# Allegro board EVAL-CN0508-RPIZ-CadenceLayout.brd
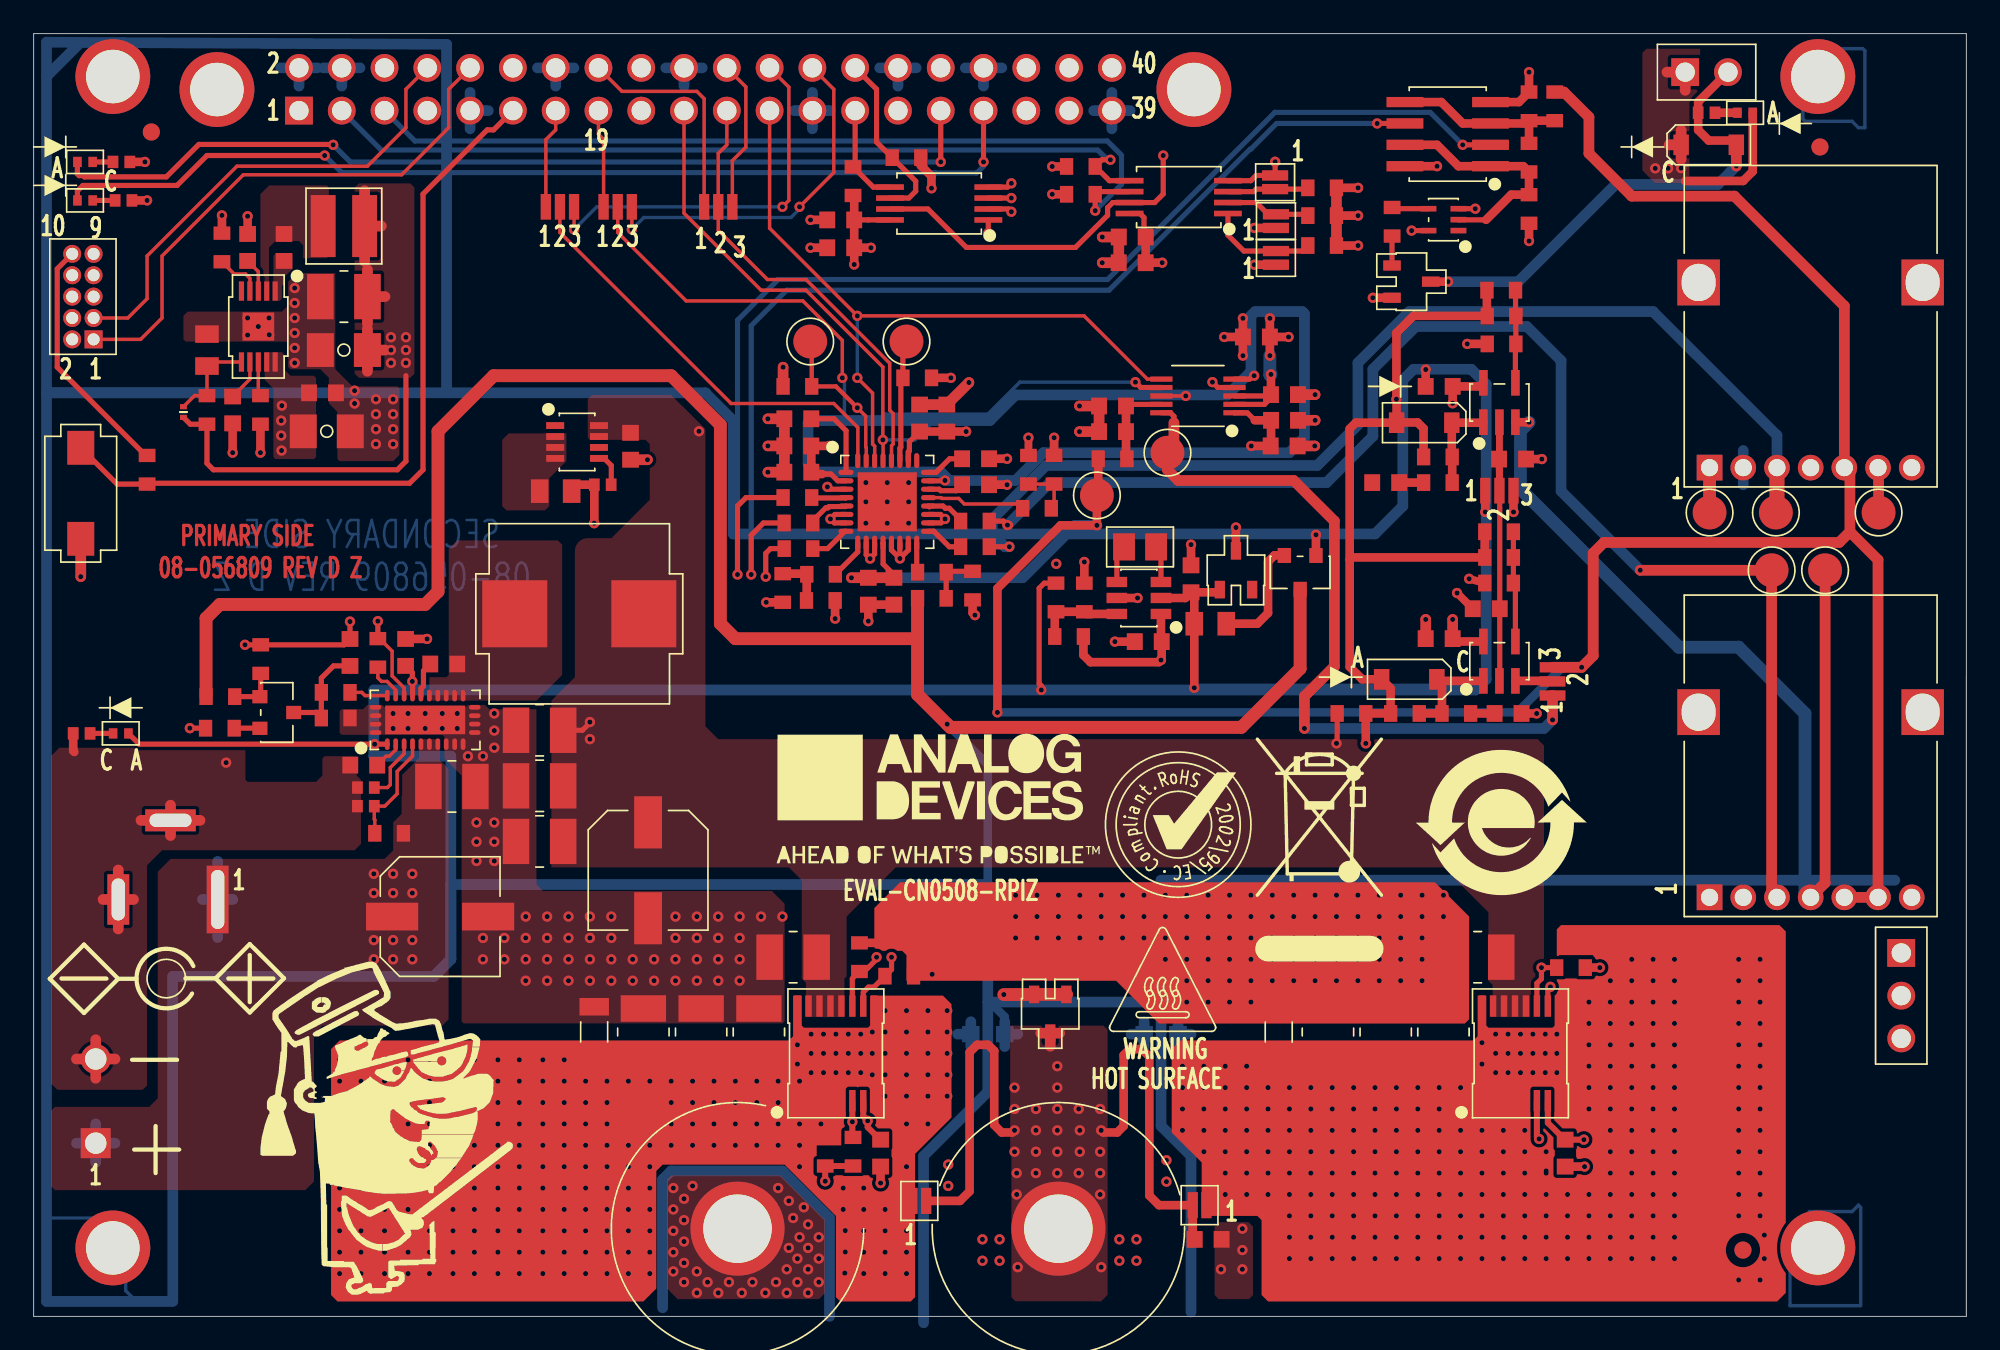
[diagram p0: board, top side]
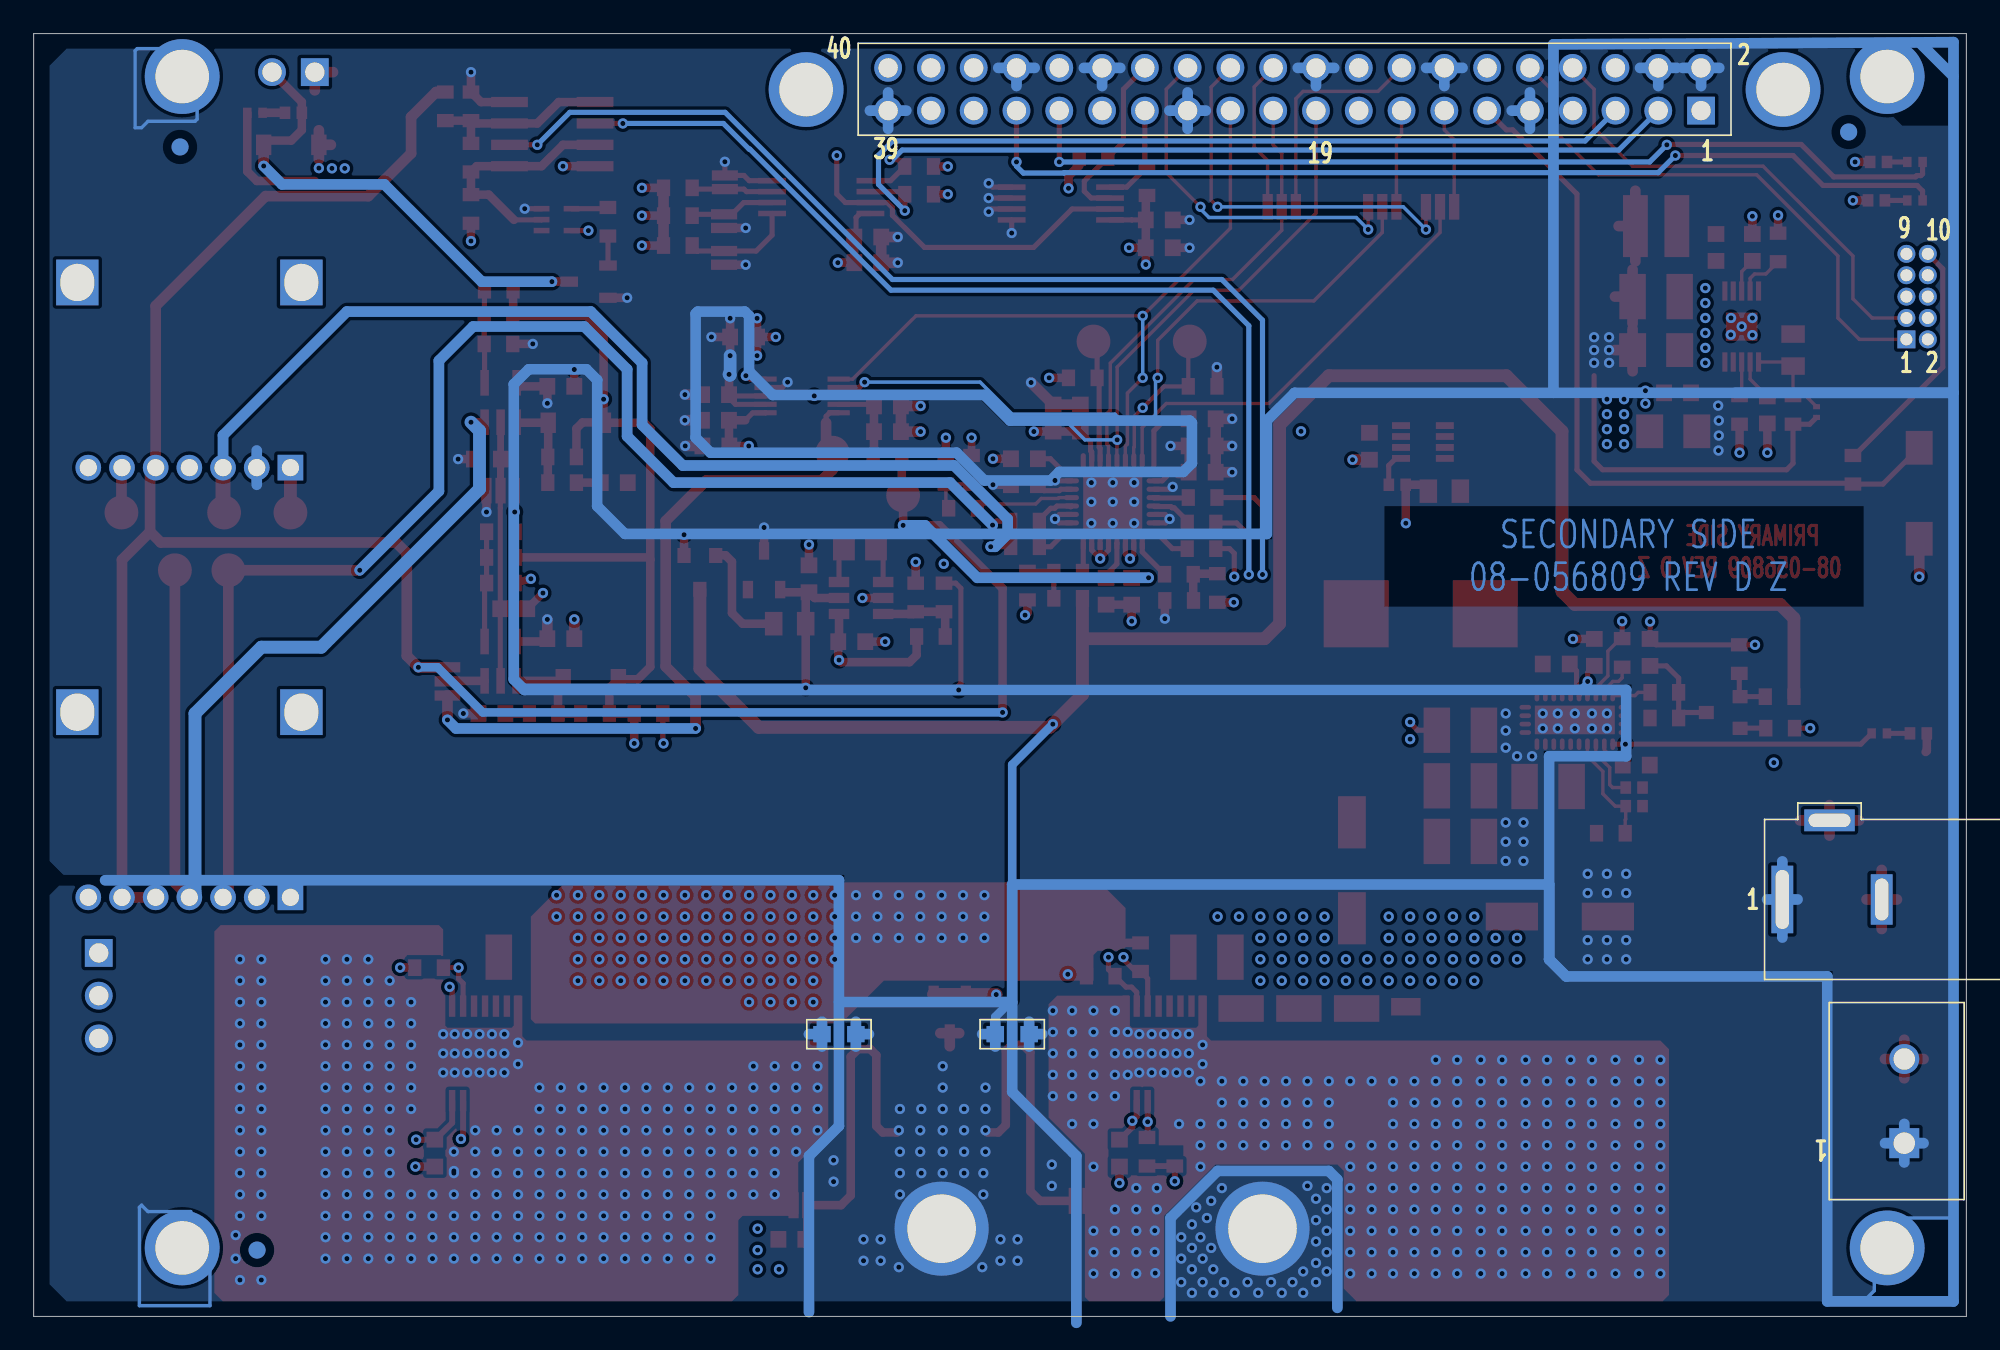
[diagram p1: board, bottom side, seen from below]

Outline 114.73 x 76.2 mm; copper layers: TOP, L2_GND, L3_VCC, BOTTOM. Coordinates in mm from the lower left corner of the outline.
Outline path: 0,76.2 0,0 114.73,0 114.73,76.2 0,76.2

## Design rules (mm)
constraint set DEFAULT: min track width 0.203

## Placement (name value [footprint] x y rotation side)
A1  LT6015IS5#TRMPBF  [SOT23-5L]  87.01 54.29 0 top
A2  LT6015IS5#TRMPBF  [SOT23-5L]  87.01 38.92 0 top
AGND  CT2236-0  [CNCALCT2236-X]  41.78 5.21 0 top
C1  22UF  [CPLSMSQ260H315]  24.13 23.75 0 top
C2  10UF  [C1210-2]  24.83 31.48 0 top
C3  0.1UF  [C0603]  19.6 32.75 180 top
C4  0.1UF  [C0603]  24.34 38.75 0 top
C5  1UF  [C0603]  22.08 39.44 90 top
C6  1NF  [C0603]  18.78 39.44 90 top
C7  100UF  [CPLSMSQ260H315]  36.47 26.5 270 top
C8  10UF  [C1210-2]  30.04 34.82 180 top
C9  10UF  [C1210-2]  30.04 31.52 180 top
C10  10UF  [C1210-2]  30.04 28.21 180 top
C11  0.01UF  [C0603]  50.28 9.7 90 top
C12  10UF  [C1210-2]  85.72 21.34 180 top
C13  0.01UF  [C0603]  90.92 9.7 90 top
C14  10UF  [C1210-2]  45.09 21.34 180 top
C15  10UF  [C1210-2]  83.69 16.89 90 top
C16  10UF  [C1210-2]  43.05 16.89 90 top
C17  10UF  [C1210-2]  76.83 16.89 90 top
C18  10UF  [C1210-2]  39.62 16.89 90 top
C19  10UF  [C1210-2]  80.26 16.89 90 top
C20  10UF  [C1210-2]  36.2 16.89 90 top
C21  1UF  [C0603]  69.72 4.57 180 top
C22  0.1UF  [C0603]  65.22 64.12 180 top
C23  10uF  [C0603]  65.21 62.59 180 top
C24  0.1UF  [C0603]  47.91 65.14 180 top
C25  4.7UF  [C1206H71]  17.4 52.58 0 top
C26  0.1UF  [C0603]  17.14 54.86 0 top
C27  1UF  [C0603]  12.7 63.5 90 top
C28  0.01UF  [C0603]  11.81 53.85 270 top
C29  0.1UF  [C0603]  83.44 40.26 0 top
C30  0.1UF  [C0603]  86.23 42.04 0 top
C31  0.22UF  [C0603]  14.86 63.5 270 top
C32  10pF  [C0201]  8.89 53.72 270 top
C33  0.1UF  [C0603]  83.44 55.24 0 top
C34  0.1UF  [C0603]  87.8 50.93 180 top
C35  47uF  [C1210-2]  18.41 60.58 180 top
C36  4.7UF  [C1206H71]  18.41 57.4 180 top
C37  10uF  [C0603]  66.17 40.08 0 top
C38  0.22UF  [C0603]  87.53 35.81 180 top
C39  0.22UF  [C0603]  80.26 49.53 0 top
C40  2.2UF  [C0805H53]  65.68 45.71 180 top
C41  10uF  [C0603]  68.71 43.81 90 top
C42  1UF  [C0603]  35.43 51.69 270 top
C43  0.1UF  [C0603]  51.07 43.08 270 top
C44  10uF  [C0603]  49.55 43.08 270 top
C45  0.1UF  [C0603]  45.36 50.15 180 top
C46  10uF  [C0603]  47.91 63.48 180 top
C47  1UF  [C0603]  45.36 51.71 0 top
C48  0.1UF  [C0603]  52.59 53.36 270 top
C49  1UF  [C0603]  54.21 53.36 90 top
C50  0.1UF  [C0603]  55.92 49.4 180 top
C51  0.1UF  [C0603]  45.36 53.32 180 top
C52  0.1UF  [C0603]  55.92 50.95 0 top
C53  0.1UF  [C0603]  74.25 54.76 0 top
C54  0.1UF  [C0603]  74.26 53.23 0 top
C55  10uF  [C0603]  74.23 51.71 0 top
C56  0.1UF  [C0603]  64.05 54.08 180 top
C57  10uF  [C0603]  64.05 52.56 180 top
D1  BAT54SLT1G  [SOT23_B]  60.35 17.97 180 top
D2  1N4148W-7-F  [SOD123-2]  81.66 37.85 180 top
D3  1N4148W-7-F  [SOD123-2]  82.55 53.09 180 top
D4  BAT54SLT1G  [SOT23_B]  71.37 44.32 0 top
D5  1N4148W-7-F  [SOD123-2]  99.44 69.6 0 top
DS1  SML-P11MTT86RR  [LED0402]  5.17 34.63 0 top
DS2  SML-P11VTT86  [LED0402]  3.05 68.58 180 top
DS3  SML-P11MTT86RR  [LED0402]  3.05 66.29 180 top
DS4  SML-P11DTT86R  [LED0402]  101.6 71.5 0 top
E1  220OHM AT 100MEGHZ  [L0603]  72.59 58.18 0 top
JP1  3PIN_SOLDER_JUMPER  [JPRSLD03]  87.01 49.05 0 top
JP2  3PIN_SOLDER_JUMPER  [JPRSLD03]  31.24 65.91 0 top
JP3  3PIN_SOLDER_JUMPER  [JPRSLD03]  34.67 65.91 0 top
JP4  3PIN_SOLDER_JUMPER  [JPRSLD03]  40.64 65.91 0 top
JP5  3PIN_SOLDER_JUMPER  [JPRSLD03]  90.17 37.72 90 top
L1  5.5UH  [LSMSQ402H197]  32.39 41.74 180 top
L2  2.2uH  [LSMSQ157H83]  18.41 64.77 0 top
NOREF  -  [unnamed]  4.7 73.65 0 top
NOREF#2  -  [#2]  -152.4 304.17 0 top
NOREF#3  -  [#2]  0 0 0 top
NOREF#4  -  [#2]  38.86 105.66 0 top
NOREF#5  -  [#2]  42.67 2.79 0 top
NOREF#6  -  [unnamed]  6.98 70.36 0 top
NOREF#7  -  [unnamed]  101.47 3.94 0 top
NOREF#8  -  [#2]  64.14 17.02 0 top
NOREF#9  -  [#2]  0 76.2 0 top
NOREF#10  -  [#2]  15.75 71.63 0 top
NOREF#11  -  [#2]  62.36 3.43 0 top
NOREF#12  -  [#2]  114.73 76.2 180 top
NOREF#13  -  [#2]  4.57 75.18 0 top
NOREF#14  -  [#2]  20.95 11.18 0 top
NOREF#15  -  [#2]  0 76.2 0 top
NOREF#16  -  [unnamed]  105.92 73.65 0 top
NOREF#17  -  [#2]  -216.53 -147.96 0 top
NOREF#18  -  [#2]  53.72 30.73 0 top
NOREF#19  -  [#2]  108.33 34.04 0 top
NOREF#20  -  [unnamed]  4.7 4.06 0 top
NOREF#21  -  [#2]  104.77 71.75 180 top
NOREF#22  -  [#2]  0 0 0 top
NOREF#23  -  [#2]  -216.53 -147.96 0 top
NOREF#24  -  [#2]  114.73 0 0 top
NOREF#25  -  [#2]  4.7 4.06 0 top
NOREF#26  -  [#2]  114.73 0 90 top
NOREF#27  -  [#2]  38.86 98.68 0 top
NOREF#28  -  [#2]  0 76.2 270 top
NOREF#29  -  [unnamed]  10.88 72.88 0 top
NOREF#30  -  [#2]  128.91 160.66 0 top
NOREF#31  -  [#2]  149.86 329.56 0 top
NOREF#32  -  [#2]  -65.53 32.26 270 top
NOREF#33  -  [#2]  203.96 -45.21 0 top
NOREF#34  -  [#2]  67.95 29.21 0 top
NOREF#35  -  [#2]  59.82 89.03 0 top
NOREF#36  -  [#2]  87.12 29.34 0 top
NOREF#37  -  [#2]  155.58 74.68 0 top
NOREF#38  -  [unnamed]  106.05 69.47 0 top
NOREF#39  -  [#2]  -216.53 -147.96 0 top
NOREF#40  -  [#2]  85.6 37.97 0 top
NOREF#41  -  [#2]  114.73 0 90 top
NOREF#42  -  [unnamed]  68.88 72.88 0 top
NOREF#43  -  [#2]  0 0 0 top
NOREF#44  -  [unnamed]  105.92 4.06 0 top
NOREF#45  -  [#2]  4.7 4.06 0 top
NOREF#46  -  [#2]  110.04 75.14 0 top
NOREF#47  -  [unnamed]  101.47 3.94 180 bottom
NOREF#48  -  [#2]  92.71 77.08 270 bottom
NOREF#49  -  [#2]  15.75 74.17 270 bottom
NOREF#50  -  [unnamed]  6.98 70.36 180 bottom
NOREF#51  -  [unnamed]  106.05 69.47 180 bottom
P1  OSTTC020162  [CNOSTTC0201X2]  3.68 10.29 90 bottom
P2  54-00130  [CNTENSILITY54-00130]  10.92 24.77 180 bottom
P3  SSQ-120-03-T-D  [CNTHFHDR2X20L2020W195H340]  15.75 71.63 0 bottom
P4  -  [JPSLD02]  73.7 67.37 270 top
P5  -  [JPSLD02]  73.75 65.06 90 top
P6  -  [JPSLD02]  73.75 62.88 90 top
P7  -  [JPSLD02]  69.22 6.6 180 top
P8  -  [JPSLD02]  52.58 6.86 0 top
P9  M20-9990346  [CNHDR1X3H340]  110.87 21.59 270 top
P10  FTSH-105-01-L-D  [CNHDR2X5H219]  3.56 58.04 90 top
P12  M20-9990246  [CNHARWIN-M20-9990246]  98.04 73.91 0 top
Q1  MMBT3906-7-F  [SOT23-M3]  14.43 35.87 270 top
Q2  FMMT493TA  [SOT23-M3]  75.18 44.2 180 top
Q3  DMG2302UQ-7  [SOT23_B]  81.79 61.47 270 top
R1  60.4K  [R0402]  19.72 31.41 0 top
R2  499K  [R0603]  21.1 28.7 0 top
R3  54.9K  [R0402]  19.72 30.31 0 top
R4  5.11K  [R0603]  20.43 39.41 90 top
R5  0  [R0603]  17.93 37.07 180 top
R6  4.99K  [R0603]  17.93 35.54 0 top
R7  1K  [R0603]  11.05 34.94 0 top
R8  100K  [R0603]  13.48 39.04 270 top
R9  100K  [R0603]  11.08 36.81 180 top
R10  1K  [R0603]  91.26 20.72 0 top
R11  1K  [R0603]  51.38 20.21 0 top
R12  3.92K  [R0603]  46.99 9.78 90 top
R13  100  [R0603]  48.64 9.78 270 top
R14  5K  [POTTTELECTP140KH]  99.49 50.42 0 top
R15  10K  [R1206]  73.91 16.89 90 top
R16  10K  [R1206]  33.27 16.89 90 top
R17  0.01  [R0603H26]  66.93 16.76 180 bottom
R18  0.01  [R0603H26]  56.64 16.76 0 bottom
R19  10K  [R0603]  6.73 50.29 270 top
R20  3.48K  [R0402]  5.21 68.58 180 top
R21  3.48K  [R0402]  5.33 66.29 180 top
R22  18.2K  [R0603]  11.18 63.5 90 top
R23  187K  [R0805]  10.29 57.4 90 top
R24  49.9K  [R0603]  13.46 53.85 270 top
R25  1MEG  [R0603]  10.29 53.85 270 top
R26  10K  [R0603]  87 43.56 180 top
R27  10K  [R0603]  87.14 57.77 180 top
R28  1K  [R0603]  60.69 42.71 270 top
R29  100K  [R0603]  87 45.09 180 top
R30  100K  [R0603]  87.14 59.42 180 top
R31  1K  [R0603]  61.47 40.39 180 top
R32  10K  [R0603]  62.37 42.71 90 top
R33  150  [R0603]  84.45 35.81 180 top
R34  150  [R0603]  83.36 49.53 0 top
R35  0  [R0603]  83.36 51.05 180 top
R36  10K  [R0603]  76.49 67.04 180 top
R37  10K  [R0603]  76.49 65.39 180 top
R38  10K  [R0603]  76.49 63.61 180 top
R39  10K  [R0603]  62.17 68.31 180 top
R40  10K  [R0603]  62.17 66.66 180 top
R41  0  [R0603]  81.41 35.81 180 top
R42  10K  [R0603]  78.23 35.81 0 top
R43  5K  [POTTTELECTP140KH]  99.49 24.89 0 top
R44  549  [R0805]  69.85 41.15 0 top
R45  47.5K  [R0402]  33.78 49.4 0 top
R46  3.48K  [R0402]  2.85 34.63 0 top
R47  200  [R0805]  30.99 49.02 0 top
R48  20K  [R0603]  46.73 42.53 180 top
R49  1.5K  [R0603]  44.47 43.27 270 top
R50  0  [R0603]  46.74 44.08 0 top
R51  1K  [R0603]  49.02 21.34 90 top
R52  20K  [R0603]  53.32 42.66 0 top
R53  2.1K  [R0603]  55.74 43.41 270 top
R54  10K  [R0603]  52.45 55.75 180 top
R55  0  [R0603]  53.32 44.21 180 top
R56  0  [R0603]  45.4 47.13 0 top
R57  20K  [R0603]  60.58 50.29 270 top
R58  1.5K  [R0603]  59.05 50.29 90 top
R59  0  [R0603]  45.34 48.64 0 top
R60  0  [R0603]  45.4 45.61 0 top
R61  0  [R0603]  55.88 45.72 180 top
R62  0  [R0603]  59.56 48.01 180 top
R63  0  [R0603]  55.88 47.24 180 top
R64  10K  [R0603]  45.34 55.24 180 top
R65  0  [R0603]  64.05 50.94 0 top
R66  20K  [R0603]  90.3 71.88 90 top
R67  499  [R0603]  88.77 71.88 270 top
R68  1MEG  [R0603]  88.77 68.83 270 top
R69  10K  [R0603]  88.77 65.79 270 top
R70  1K  [R0603]  80.64 65.02 270 top
R71  3.48K  [R0402]  99.31 71.5 0 top
R72  10K  [R0603]  48.64 67.44 90 top
R73  10K  [R0603]  51.82 68.83 180 top
R74  100K  [R0603]  87.12 60.96 180 top
R75  100K  [R0603]  87 46.61 180 top
S1  EVQPNF04M  [SWSMSPST]  2.79 48.9 90 top
TP1  SMOX/060/B1/R2K GOLD  [CNOXLEYSMOX_060_B1]  109.52 47.75 0 top
TP2  SMOX/060/B1/R2K GOLD  [CNOXLEYSMOX_060_B1]  99.49 47.75 0 top
TP3  SMOX/060/B1/R2K GOLD  [CNOXLEYSMOX_060_B1]  103.43 47.75 0 top
TP4  SMOX/060/B1/R2K GOLD  [CNOXLEYSMOX_060_B1]  106.35 44.32 0 top
TP5  SMOX/060/B1/R2K GOLD  [CNOXLEYSMOX_060_B1]  103.17 44.32 0 top
TP6  SMOX/060/B1/R2K GOLD  [CNOXLEYSMOX_060_B1]  51.82 57.91 0 top
TP7  SMOX/060/B1/R2K GOLD  [CNOXLEYSMOX_060_B1]  46.1 57.91 0 top
TP8  SMOX/060/B1/R2K GOLD  [CNOXLEYSMOX_060_B1]  67.31 51.31 0 top
TP9  SMOX/060/B1/R2K GOLD  [CNOXLEYSMOX_060_B1]  63.12 48.77 0 top
U1  LT8612EUDE#TRPBF  [QFN28_6X3_PAD4_75X1_70]  23.24 35.43 0 top
U2  LT3081EFE#PBF  [TSSOP16_PAD3_58X2_94]  47.62 15.62 0 top
U3  LT3081EFE#PBF  [TSSOP16_PAD3_58X2_94]  88.27 15.62 0 top
U4  24LC32A-I/ST  [TSSOP8]  53.75 66.11 90 top
U5  LT8609EMSE#TRPBF  [MSOP10_PAD1_88X1_68]  13.33 58.8 180 top
U6  LTC1983ES6-5#PBF  [TSOT23_6]  65.61 42.68 90 top
U7  24LC32A-I/ST  [TSSOP8]  67.98 66.49 90 top
U8  LT3092ETS8#PBF  [TSOT-8]  32.26 51.94 270 top
U9  AD7124-4BCPZ  [QFN32_5X5_PAD3_5X3_5]  50.67 48.39 270 top
U10  AD5683RBRMZ  [RM10]  69.12 54.68 90 top
U11  ADCMP392ARZ  [SO8]  83.95 70.23 90 top
U12  74AHC1G04GW,125  [SOT353]  83.69 65.15 90 top
VOUT  CT2236-0  [CNCALCT2236-X]  60.83 5.21 0 top

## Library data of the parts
A1 A2 = ADLT6015: User Part Number: UPN; Tolerance: N/A; alternate symbols: (); part number: ADLT6015_SM-LT6015IS5#TRMPBF,E035084,SOT23-5L; tolerance: N/A
AGND VOUT = CNTP1P: Tolerance: N/A; User Part Number: UPN; alternate symbols: (); part number: CNTP1P_TH-CT2236-0,E036069,CNCALCT2236-X; tolerance: N/A
C1 = CAPP: Tolerance: 20; User Part Number: UPN; alternate symbols: (); part number: CAPP_SM-22UF,63V,20,E034289,CPLSMSQ260H315; tolerance: 20
C2 C8-C10 C12 C14-C20 = CAP: Tolerance: 20; User Part Number: UPN; alternate symbols: (); part number: CAP_SM-10UF,50V,20,E028935,C1210-2; tolerance: 20
C3 C4 C22 C24 C26 C29 C30 C33 C34 C43 C45 C48 C50-C54 C56 = CAP: User Part Number: UPN; Tolerance: 10; alternate symbols: (); part number: CAP_SM-0.1UF,50V,10,E028927,C0603; tolerance: 10
C5 C21 C27 C42 C47 C49 = CAP: User Part Number: UPN; Tolerance: 10; alternate symbols: (); part number: CAP_SM-1UF,50V,10,E034224,C0603; tolerance: 10
C6 = CAP: User Part Number: UPN; Tolerance: 5; alternate symbols: (); part number: CAP_SM-1NF,25V,5,E035602,C0603; tolerance: 5
C7 = CAPP: Tolerance: 20; User Part Number: UPN; alternate symbols: (); part number: CAPP_SM-100UF,35V,20,E035065,CPLSMSQ260H315; tolerance: 20
C11 C13 C28 = CAP: User Part Number: UPN; Tolerance: 10; alternate symbols: (); part number: CAP_SM-0.01UF,100V,10,E032297,C0603; tolerance: 10
C23 C37 C41 C44 C46 C55 C57 = CAP: User Part Number: UPN; Tolerance: 20; alternate symbols: (); part number: CAP_SM-10UF,6.3V,20,E007143,C0603; tolerance: 20
C25 C36 = CAP: Tolerance: 10; User Part Number: UPN; alternate symbols: (); part number: CAP_SM-4.7UF,50V,10,E026699,C1206H71; tolerance: 10
C31 C38 C39 = CAP: User Part Number: UPN; Tolerance: 10; alternate symbols: (C0603L, C0603L_ALT); part number: CAP_SM-0.22UF,25V,10,E028829,C0603; tolerance: 10
C32 = CAP: Tolerance: 5; User Part Number: UPN; alternate symbols: (C0201NC); part number: CAP_SM-10PF,25V,5,E022849,C0201; tolerance: 5
C35 = CAP: Tolerance: 10; User Part Number: UPN; alternate symbols: (); part number: CAP_SM-47UF,10V,10,E011546,C1210-2; tolerance: 10
C40 = CAP: Tolerance: 10; User Part Number: UPN; alternate symbols: (); part number: CAP_SM-2.2UF,10V,10,E028490,C0805H53; tolerance: 10
D1 D4 = DIOSCHOTTKY3P_V14: User Part Number: UPN; Tolerance: N/A; alternate symbols: (); part number: DIOSCHOTTKY3P_V14_SM-BAT54SLT1G,30V,N/A,E035143,SOT23_B; tolerance: N/A
D2 D3 D5 = DIO: User Part Number: UPN; Tolerance: N/A; alternate symbols: (); part number: DIO_SM-1N4148W-7-F,100V,N/A,E018902,SOD123-2; tolerance: N/A
DS1 DS3 = DIOLED: User Part Number: UPN; Tolerance: N/A; alternate symbols: (); part number: DIOLED_SM-SML-P11MTT86R,N/A,N/A,E014445,LED0402; tolerance: N/A
DS2 = DIOLED: User Part Number: UPN; Tolerance: N/A; alternate symbols: (); part number: DIOLED_SM-SML-P11VTT86,N/A,N/A,E019415,LED0402; tolerance: N/A
DS4 = DIOLED: User Part Number: UPN; Tolerance: N/A; alternate symbols: (); part number: DIOLED_SM-SML-P11DTT86R,1.9V,N/A,E038620,LED0402; tolerance: N/A
E1 = FERRITE: User Part Number: UPN; Tolerance: 25; alternate symbols: (); part number: FERRITE_SM-220OHM AT 100MEGHZ,25,E030348,L0603; tolerance: 25
JP1-JP5 = NC3P_JMPR: Tolerance: N/A; User Part Number: UPN; alternate symbols: (); part number: NC3P_JMPR_SM-3PIN_SOLDER_JUMPER,E005606,JPRSLD03; tolerance: N/A
L1 = IND: User Part Number: UPN; Tolerance: 20; alternate symbols: (); part number: IND_SM-5.5UH,20,E034926,LSMSQ402H197; tolerance: 20
L2 = IND: User Part Number: UPN; Tolerance: 20; alternate symbols: (); part number: IND_SM-2.2UH,20,E016651,LSMSQ157H83; tolerance: 20
P1 = CN2P: Tolerance: N/A; User Part Number: UPN; alternate symbols: (); part number: CN2P_TH-OSTTC020162,E034806,CNOSTTC0201X2; tolerance: N/A
P2 = CN3P_V6: User Part Number: UPN; Tolerance: N/A; alternate symbols: (); part number: CN3P_V6_TH-54-00130,E035595,CNTENSILITY54-00130; tolerance: N/A
P3 = CN40P_V2: User Part Number: UPN; Tolerance: N/A; alternate symbols: (); part number: CN40P_V2_TH-SSQ-120-03-T-D,E033992,CNTHFHDR2X20L2020W195H340; tolerance: N/A
P4-P8 = NC2P: User Part Number: UPN; Tolerance: N/A; alternate symbols: (); part number: NC2P_SM-JPSLD02,E006230,JPSLD02; tolerance: N/A
P9 = CN3P: Tolerance: N/A; User Part Number: UPN; alternate symbols: (); part number: CN3P_TH-M20-9990346,E017878,CNHDR1X3H340; tolerance: N/A
P10 = CN10P_ODD_EVEN: Tolerance: N/A; User Part Number: UPN; alternate symbols: (); part number: CN10P_ODD_EVEN_TH-FTSH-105-01-L-D,E018623,CNHDR2X5H219; tolerance: N/A
P12 = CN2P: Tolerance: N/A; User Part Number: UPN; alternate symbols: (); part number: CN2P_TH-M20-9990246,E010843,CNHARWIN-M20-9990246; tolerance: N/A
Q1 = TRANPNP_V3: User Part Number: UPN; Tolerance: N/A; alternate symbols: (); part number: TRANPNP_V3_SM-MMBT3906-7-F,E034958,SOT23-M3; tolerance: N/A
Q2 = TRANNPN_V2: User Part Number: UPN; Tolerance: N/A; alternate symbols: (); part number: TRANNPN_V2_SM-FMMT493TA,E034957,SOT23-M3; tolerance: N/A
Q3 = TRANNMOSFET_V8: User Part Number: UPN; Tolerance: N/A; alternate symbols: (); part number: TRANNMOSFET_V8_SM-DMG2302UQ-7,E039514,SOT23_B; tolerance: N/A
R1 = RES: User Part Number: UPN; Tolerance: 1; alternate symbols: (R0402L); part number: RES_SM-60.4K,E022436,1/10W,1,R0402; tolerance: 1
R2 = RES: User Part Number: UPN; Tolerance: 1; alternate symbols: (R0603L); part number: RES_SM-499K,E015340,1/10W,1,R0603; tolerance: 1
R3 = RES: User Part Number: UPN; Tolerance: 1; alternate symbols: (R0402L); part number: RES_SM-54.9K,E023190,1/10W,1,R0402; tolerance: 1
R4 = RES: User Part Number: UPN; Tolerance: 1; alternate symbols: (R0603L); part number: RES_SM-5.11K,E026136,1/10W,1,R0603; tolerance: 1
R5 R35 R41 R50 R55 R56 R59-R63 R65 = RES: User Part Number: UPN; Tolerance: 5; alternate symbols: (R0603L); part number: RES_SM-0,E006826,1/10W,5,R0603; tolerance: 5
R6 = RES: User Part Number: UPN; Tolerance: 1; alternate symbols: (R0603L); part number: RES_SM-4.99K,E003726,1/10W,1,R0603; tolerance: 1
R7 R10 R11 R28 R31 R51 R70 = RES: User Part Number: UPN; Tolerance: 1; alternate symbols: (R0603L); part number: RES_SM-1K,E003678,1/10W,1,R0603; tolerance: 1
R8 R9 R29 R30 R74 R75 = RES: User Part Number: UPN; Tolerance: 1; alternate symbols: (R0603L); part number: RES_SM-100K,E010279,1/10W,1,R0603; tolerance: 1
R12 = RES: User Part Number: UPN; Tolerance: 1; alternate symbols: (); part number: RES_SM-3.92K,E035877,1/10W,1,R0603; tolerance: 1
R13 = RES: User Part Number: UPN; Tolerance: 1; alternate symbols: (R0603L); part number: RES_SM-100,E003668,1/10W,1,R0603; tolerance: 1
R14 R43 = RESVAR_7P: User Part Number: UPN; Tolerance: 20; alternate symbols: (); part number: RESVAR_7P_TH-5K,E035577,1/20W,20,POTTTELECTP140KH; tolerance: 20
R15 R16 = RES: User Part Number: UPN; Tolerance: 1; alternate symbols: (); part number: RES_SM-10K,E003285,1/4W,1,R1206; tolerance: 1
R17 R18 = RES: User Part Number: UPN; Tolerance: 1; alternate symbols: (); part number: RES_SM-0.01,E029734,1/4W,1,R0603H26; tolerance: 1
R19 R26 R27 R32 R36-R40 R42 R54 R64 R69 R72 R73 = RES: User Part Number: UPN; Tolerance: 1; alternate symbols: (R0603L); part number: RES_SM-10K,E003671,1/10W,1,R0603; tolerance: 1
R20 R21 R46 R71 = RES: User Part Number: UPN; Tolerance: 1; alternate symbols: (R0402L); part number: RES_SM-3.48K,E023793,1/10W,1,R0402; tolerance: 1
R22 = RES: User Part Number: UPN; Tolerance: 1; alternate symbols: (R0603L); part number: RES_SM-18.2K,E011126,1/10W,1,R0603; tolerance: 1
R23 = RES: User Part Number: UPN; Tolerance: 1; alternate symbols: (R0805L); part number: RES_SM-187K,E015129,1/8W,1,R0805; tolerance: 1
R24 = RES: User Part Number: UPN; Tolerance: 1; alternate symbols: (R0603L); part number: RES_SM-49.9K,E015342,1/10W,1,R0603; tolerance: 1
R25 R68 = RES: User Part Number: UPN; Tolerance: 1; alternate symbols: (R0603L); part number: RES_SM-1MEG,E003682,1/10W,1,R0603; tolerance: 1
R33 R34 = RES: User Part Number: UPN; Tolerance: 1; alternate symbols: (R0603L); part number: RES_SM-150,E003691,1/10W,1,R0603; tolerance: 1
R44 = RES: User Part Number: UPN; Tolerance: 1; alternate symbols: (R0805L); part number: RES_SM-549,E003594,1/8W,1,R0805; tolerance: 1
R45 = RES: User Part Number: UPN; Tolerance: 1; alternate symbols: (R0402L); part number: RES_SM-47.5K,E013598,1/10W,1,R0402; tolerance: 1
R47 = RES: User Part Number: UPN; Tolerance: 1; alternate symbols: (R0805L); part number: RES_SM-200,E003604,1/8W,1,R0805; tolerance: 1
R48 R52 R57 R66 = RES: User Part Number: UPN; Tolerance: 1; alternate symbols: (R0603L); part number: RES_SM-20K,E017927,1/10W,1,R0603; tolerance: 1
R49 R58 = RES: User Part Number: UPN; Tolerance: 1; alternate symbols: (R0603L); part number: RES_SM-1.5K,E003704,1/10W,1,R0603; tolerance: 1
R53 = RES: User Part Number: UPN; Tolerance: 1; alternate symbols: (R0603L); part number: RES_SM-2.1K,E011132,1/10W,1,R0603; tolerance: 1
R67 = RES: User Part Number: UPN; Tolerance: 1; alternate symbols: (R0603L); part number: RES_SM-499,E003667,1/10W,1,R0603; tolerance: 1
S1 = SWSPST2PIN_V2: Tolerance: N/A; User Part Number: UPN; alternate symbols: (); part number: SWSPST2PIN_V2_SM-EVQPNF04M,E007214,SWSMSPST; tolerance: N/A
TP1-TP9 = CNTP1P: Tolerance: N/A; User Part Number: UPN; alternate symbols: (); part number: CNTP1P_SM-GOLD,E023771,CNOXLEYSMOX_060_B1; tolerance: N/A
U1 = ADLT8612: Tolerance: N/A; User Part Number: UPN; alternate symbols: (); part number: ADLT8612_SM-LT8612EUDE#TRPBF,E034476,QFN28_6X3_PAD4_75X1_70; tolerance: N/A
U2 U3 = ADLT3081_V2: User Part Number: UPN; Tolerance: N/A; alternate symbols: (); part number: ADLT3081_V2_SM-LT3081EFE#PBF,E034874,TSSOP16_PAD3_58X2_94; tolerance: N/A
U4 U7 = IC24FC256: Tolerance: N/A; User Part Number: UPN; alternate symbols: (); part number: IC24FC256_SM-24LC32A-I/ST,E014553,TSSOP8; tolerance: N/A
U5 = ADLT8609: User Part Number: UPN; Tolerance: N/A; alternate symbols: (); part number: ADLT8609_SM-LT8609EMSE#TRPBF,E035643,MSOP10_PAD1_88X1_68; tolerance: N/A
U6 = ADLTC1983_X: User Part Number: UPN; Tolerance: N/A; alternate symbols: (); part number: ADLTC1983_X_SM-LTC1983ES6-5#PBF,E034952,TSOT23_6; tolerance: N/A
U8 = LINLT3092: User Part Number: UPN; Tolerance: N/A; alternate symbols: (); part number: LINLT3092_SM-LT3092ETS8#PBF,E030126,TSOT-8; tolerance: N/A
U9 = AD7124_4: Tolerance: N/A; User Part Number: UPN; alternate symbols: (); part number: AD7124_4_SM-AD7124-4BCPZ,E019053,QFN32_5X5_PAD3_5X3_5; tolerance: N/A
U10 = AD568XR_V2: Tolerance: N/A; User Part Number: UPN; alternate symbols: (); part number: AD568XR_V2_SM-AD5683RBRMZ,E017322,RM10; tolerance: N/A
U11 = ADCMP392: Tolerance: N/A; User Part Number: UPN; alternate symbols: (); part number: ADCMP392_SM-ADCMP392ARZ,E018932,SO8; tolerance: N/A
U12 = 741G04: User Part Number: UPN; Tolerance: N/A; alternate symbols: (); part number: 741G04_SM-74AHC1G04GW,125,E020844,SOT353; tolerance: N/A

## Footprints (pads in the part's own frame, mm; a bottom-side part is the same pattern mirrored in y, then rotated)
C0201
  rect 0.305x0.406 smd: 1(-0.318,0) 2(0.318,0)
C0603
  rect 0.94x0.991 smd: 1(-0.8,0) 2(0.8,0)
C0805H53
  rect 1.295x1.6 smd: 1(-0.953,0) 2(0.953,0)
C1206H71
  rect 1.6x2.007 smd: 1(-1.397,0) 2(1.397,0)
C1210-2
  rect 1.575x2.692 smd: 1(-1.397,0) 2(1.397,0)
CNCALCT2236-X
  round 5.588 hole 4.064: 1(0,0)
CNHARWIN-M20-9990246
  rect 1.651x1.651 hole 1.143: 1(0,0)
  round 1.651 hole 1.143: 2(2.54,0)
CNHDR1X3H340
  rect 1.651x1.651 hole 1.143: 1(0,0)
  round 1.651 hole 1.143: 2(2.54,0) 3(5.08,0)
CNHDR2X5H219
  rect 1.067x1.067 hole 0.711: 1(0,0)
  round 1.067 hole 0.711: 2(0,1.27) 3(1.27,0) 4(1.27,1.27) 5(2.54,0) 6(2.54,1.27) 7(3.81,0) 8(3.81,1.27) 9(5.08,0) 10(5.08,1.27)
CNOSTTC0201X2
  rect 1.778x1.778 hole 1.27: 1(0,0)
  round 1.778 hole 1.27: 2(5,0)
CNOXLEYSMOX_060_B1
  round 2.007 smd: 1(0,0)
CNTENSILITY54-00130
  rect 1.295x4.013 hole 0.787x3.505: 1(0,0)
  rect 1.295x2.997 hole 0.787x2.489: 2(5.9,0)
  rect 2.997x1.295 hole 2.489x0.787: 3(2.8,4.7)
CNTHFHDR2X20L2020W195H340
  rect 1.651x1.651 hole 1.143: 1(0,0)
  round 1.651 hole 1.143: 2(0,-2.54) 3(2.54,0) 4(2.54,-2.54) 5(5.08,0) 6(5.08,-2.54) 7(7.62,0) 8(7.62,-2.54) 9(10.16,0) 10(10.16,-2.54) 11(12.7,0) 12(12.7,-2.54) 13(15.24,0) 14(15.24,-2.54) 15(17.78,0) 16(17.78,-2.54) 17(20.32,0) 18(20.32,-2.54) 19(22.86,0) 20(22.86,-2.54) 21(25.4,0) 22(25.4,-2.54) 23(27.94,0) 24(27.94,-2.54) 25(30.48,0) 26(30.48,-2.54) 27(33.02,0) 28(33.02,-2.54) 29(35.56,0) 30(35.56,-2.54) 31(38.1,0) 32(38.1,-2.54) 33(40.64,0) 34(40.64,-2.54) 35(43.18,0) 36(43.18,-2.54) 37(45.72,0) 38(45.72,-2.54) 39(48.26,0) 40(48.26,-2.54)
CPLSMSQ260H315
  rect 3.099x1.651 smd: N(2.85,0) P(-2.85,0)
JPRSLD03
  rect 0.61x1.524 smd: 1(-0.838,0) 2(0,0) 3(0.838,0)
JPSLD02
  rect 0.61x1.549 smd: 1(-0.406,0) 2(0.406,0)
L0603
  rect 0.94x0.991 smd: 1(-0.8,0) 2(0.8,0)
LED0402
  rect 0.508x0.61 smd: A(0.454,0) C(-0.454,0)
LSMSQ157H83
  rect 1.473x3.683 smd: 1(-1.232,0) 2(1.232,0)
LSMSQ402H197
  rect 3.861x3.988 smd: 1(-3.83,0) 2(3.83,0)
MSOP10_PAD1_88X1_68
  rect 0.305x1.143 smd: 1(-1,-2.106) 2(-0.5,-2.106) 3(0,-2.106) 4(0.5,-2.106) 5(1,-2.106) 6(1,2.106) 7(0.5,2.106) 8(0,2.106) 9(-0.5,2.106) 10(-1,2.106)
  rect 1.88x1.676 smd: PAD(0,0)
POTTTELECTP140KH
  rect 2.515x2.718 hole 2.007x2.21: (-0.65,11) (12.65,11)
  rect 1.524x1.524 hole 1.016: 1(0,0)
  round 1.524 hole 1.016: 2(2,0) 3(4,0) 4(6,0) 5(8,0) 6(10,0) 7(12,0)
QFN28_6X3_PAD4_75X1_70
  oval 0.279x0.686 smd: 1(-2.25,-1.443) 2(-1.75,-1.443) 3(-1.25,-1.443) 4(-0.75,-1.443) 5(-0.25,-1.443) 6(0.25,-1.443) 7(0.75,-1.443) 8(1.25,-1.443) 9(1.75,-1.443) 10(2.25,-1.443) 15(2.25,1.443) 16(1.75,1.443) 17(1.25,1.443) 18(0.75,1.443) 19(0.25,1.443) 20(-0.25,1.443) 21(-0.75,1.443) 22(-1.25,1.443) 23(-1.75,1.443) 24(-2.25,1.443)
  oval 0.686x0.279 smd: 11(2.943,-0.75) 12(2.943,-0.25) 13(2.943,0.25) 14(2.943,0.75) 25(-2.943,0.75) 26(-2.943,0.25) 27(-2.943,-0.25) 28(-2.943,-0.75)
  rect 4.75x1.702 smd: PAD(0,0)
QFN32_5X5_PAD3_5X3_5
  oval 0.305x0.889 smd: 1(-1.75,-2.45) 2(-1.25,-2.45) 3(-0.75,-2.45) 4(-0.25,-2.45) 5(0.25,-2.45) 6(0.75,-2.45) 7(1.25,-2.45) 8(1.75,-2.45) 17(1.75,2.45) 18(1.25,2.45) 19(0.75,2.45) 20(0.25,2.45) 21(-0.25,2.45) 22(-0.75,2.45) 23(-1.25,2.45) 24(-1.75,2.45)
  oval 0.889x0.305 smd: 9(2.45,-1.75) 10(2.45,-1.25) 11(2.45,-0.75) 12(2.45,-0.25) 13(2.45,0.25) 14(2.45,0.75) 15(2.45,1.25) 16(2.45,1.75) 25(-2.45,1.75) 26(-2.45,1.25) 27(-2.45,0.75) 28(-2.45,0.25) 29(-2.45,-0.25) 30(-2.45,-0.75) 31(-2.45,-1.25) 32(-2.45,-1.75)
  rect 3.505x3.505 smd: PAD(0,0)
R0402
  rect 0.635x0.737 smd: 1(-0.5,0) 2(0.5,0)
R0603
  rect 0.787x0.991 smd: 1(-0.85,0) 2(0.85,0)
R0603H26
  rect 1.041x0.965 smd: 1(-1.006,0) 2(1.006,0)
R0805
  rect 1.041x1.397 smd: 1(-0.95,0) 2(0.95,0)
R1206
  rect 1.041x1.753 smd: 1(-1.5,0) 2(1.5,0)
RM10
  rect 0.305x1.321 smd: 1(-1,-2.171) 2(-0.5,-2.171) 3(0,-2.171) 4(0.5,-2.171) 5(1,-2.171) 6(1,2.171) 7(0.5,2.171) 8(0,2.171) 9(-0.5,2.171) 10(-1,2.171)
SO8
  rect 0.61x2.184 smd: 1(-1.905,-2.54) 2(-0.635,-2.54) 3(0.635,-2.54) 4(1.905,-2.54) 5(1.905,2.54) 6(0.635,2.54) 7(-0.635,2.54) 8(-1.905,2.54)
SOD123-2
  rect 0.914x1.219 smd: A(1.638,0) C(-1.638,0)
SOT23-5L
  rect 0.508x1.524 smd: 1(-0.95,-1.17) 2(0,-1.17) 3(0.95,-1.17) 4(0.95,1.17) 5(-0.95,1.17)
SOT23-M3
  rect 0.787x0.889 smd: 1(-0.94,-1.003) 2(0.94,-1.003) 3(0,1.003)
SOT23_B
  rect 0.61x1.041 smd: 1(-0.958,-1.15) 2(0.958,-1.15) 3(0,1.15)
SOT353
  rect 0.33x0.94 smd: 1(-0.65,-0.89) 2(0,-0.89) 3(0.65,-0.89) 4(0.65,0.89) 5(-0.65,0.89)
SWSMSPST
  rect 2.007x1.6 smd: 1(-2.703,0) 2(2.703,0)
TSOT23_6
  rect 0.61x1.219 smd: 1(-0.95,-1.31) 2(0,-1.31) 3(0.95,-1.31) 4(0.95,1.31) 5(0,1.31) 6(-0.95,1.31)
TSOT-8
  rect 0.406x1.067 smd: 1(-0.975,-1.3) 2(-0.325,-1.3) 3(0.325,-1.3) 4(0.975,-1.3) 5(0.975,1.3) 6(0.325,1.3) 7(-0.325,1.3) 8(-0.975,1.3)
TSSOP8
  rect 0.33x1.651 smd: 1(-0.975,-2.92) 2(-0.325,-2.92) 3(0.325,-2.92) 4(0.975,-2.92) 5(0.975,2.92) 6(0.325,2.92) 7(-0.325,2.92) 8(-0.975,2.92)
TSSOP16_PAD3_58X2_94
  rect 0.381x1.27 smd: 1(-2.275,-2.81) 2(-1.625,-2.81) 3(-0.975,-2.81) 4(-0.325,-2.81) 5(0.325,-2.81) 6(0.975,-2.81) 7(1.625,-2.81) 8(2.275,-2.81) 9(2.275,2.81) 10(1.625,2.81) 11(0.975,2.81) 12(0.325,2.81) 13(-0.325,2.81) 14(-0.975,2.81) 15(-1.625,2.81) 16(-2.275,2.81)
  rect 3.581x2.946 smd: PAD(0,0)
unnamed
  round 4.445 hole 3.175 unplated: (0,0)

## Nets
3V3A: C22.1 C23.1 C24.1 C46.1 C48.2(N2) C49.1 C54.1 C55.1 E1.1 P3.1 P3.17 P9.1 P10.10(N5) R19.1 R36.1 R37.1 R38.1 R39.2(N2) R40.2(N2) R54.1 R72.1 R73.1 U4.8 U7.8 U9.26 U10.1
3V3D: C45.1 C47.2(N2) C53.1 E1.2(N2) U9.2 U10.2 U10.3
5V_RPI: C32.2(N2) C35.1 C36.1 C37.2(N2) D5.C DS4.A(P) L2.2(N2) P3.2 P3.4 P12.1 R24.2(N2) R25.2(N2) R31.1 R69.2(N2) U6.1 U11.8(VCC) U12.5
AGND: AGND.1(N1) C1.N(N2) C2.2(N2) C3.2(N2) C5.2(N2) C7.N(N2) C8.2(N2) C9.2(N2) C10.2(N2) C11.1 C12.2(N2) C13.1 C14.2(N2) C15.2(N2) C16.2(N2) C17.2(N2) C18.2(N2) C19.2(N2) C20.2(N2) C21.1 C22.2(N2) C23.2(N2) C24.2(N2) C25.2(N2) C26.2(N2) C27.2(N2) C28.2(N2) C29.1 C30.1 C33.1 C34.1 C35.2(N2) C36.2(N2) C37.1 C38.1 C41.2(N2) C42.2(N2) C43.2(N2) C44.2(N2) C45.2(N2) C46.2(N2) C47.1 C48.1 C49.2(N2) C50.1 C51.2(N2) C52.2(N2) C53.2(N2) C54.2(N2) C55.2(N2) C56.2(N2) C57.2(N2) D4.3(N3) JP1.3 P1.2(N2) P2.2 P2.3(N3) P3.6 P3.9 P3.14 P3.20 P3.25 P3.30 P3.34 P3.39 P4.1 P5.1 P6.1 P9.3(N3) P10.7 P10.9 Q2.1 Q3.2(S) R1.1 R3.1 R6.2(N2) R10.2(N2) R11.2(N2) R14.2 R15.2(N2) R16.2(N2) R20.1 R21.1 R22.2(N2) R23.2(N2) R26.2(N2) R27.2(N2) R32.2(N2) R43.1 R43.2 R46.1 R49.2(N2) R51.2(N2) R53.2(N2) R58.2(N2) R64.2(N2) R67.1 S1.1 U1.8 U1.9 U1.10 U1.11 U1.12 U1.13 U1.14 U1.25 U1.26 U1.27 U1.28 U1.PAD U4.1 U4.2 U4.3 U4.4 U5.PAD U6.5 U7.4 U9.3 U9.6 U9.7 U9.10 U9.11 U9.13 U9.14 U9.15 U9.18 U9.19 U9.23 U9.PAD U10.4 U10.5 U11.4 U12.3
VIN: A1.5 A2.5 C1.P C2.1 C25.1 C26.1 C29.2(N2) C33.2(N2) P1.1 P2.1 R2.2(N2) R48.1 U1.5 U1.6 U1.7(VIN_3) U5.9(VIN) U5.10
A0: P6.2(N2) R38.2(N2) U7.1
A1: P5.2(N2) R37.2(N2) U7.2
A2: P4.2(N2) R36.2(N2) U7.3
CS0: JP2.3 P3.24
CS1: JP3.3 P3.26
CS_ADC: JP2.2(COM) U9.32
CS_DAC: JP3.2(COM) U10.7
ID_SC: P3.28 R73.2(N2) U4.6
ID_SD: P3.27 R72.2(N2) U4.5
ILIM+: C16.1 C18.1 C20.1 P8.1 R12.2(N2) R14.4 R14.6 R16.1 R18.1 TP1.1(N1) U2.1 U2.2 U2.3 U2.4 U2.5 U2.8 U2.9 U2.16 U2.PAD
ILIM-: R12.1 R13.2(N2) R14.1 TP2.1(N1)
IMON: R11.1 R60.1 U2.10 U3.10
INTVCC: C5.1 DS1.A(P) R28.1 U1.1 U1.21
LDOIN: C6.2(N2) C7.P C8.1 C9.1 C10.1 C12.1 C14.1 C42.1 L1.1 R4.2(N2) R7.1 R8.1 R42.1 R57.1 U1.22 U2.12 U2.13 U2.14 U2.15 U3.12 U3.13 U3.14 U3.15 U8.7 U8.8
M5V0: C41.1 D4.1 JP1.1 R44.1 U6.2(VOUT)
MISO: JP4.2(COM) P3.21 U9.28
MOSI: P3.19 U9.29 U10.8
R_ILIM: R14.3 R61.1 TP3.1(N1)
R_VLIM: R43.3 R63.1 TP5.1(N1)
SCL_RPI: P3.5 R40.1 U7.6
SCLK: P3.23 U9.30 U10.6
SDA_RPI: P3.3 R39.1 U7.5
TEMP_1: R51.1 R59.1 U2.11(TEMP) U11.2
TEMP_2: R10.1 R56.1 U3.11(TEMP) U11.6
UART0_RX: P3.10 P10.1
UART0_TX: P3.8 P10.3
UNNAMED_2_ADLT3081V2_I39_ILIM: R13.1 U2.6 U3.6
UNNAMED_2_ADLT3081V2_I63_OUT1: C15.1 C17.1 C19.1 P7.1 R15.1 R17.1 U3.1 U3.2 U3.3 U3.4 U3.5 U3.8 U3.9 U3.16 U3.PAD
UNNAMED_2_ADLT8612_I115_BST: C4.1 U1.20
UNNAMED_2_ADLT8612_I115_FB: R5.1 U1.24
UNNAMED_2_ADLT8612_I115_PG: R4.1 U1.23
UNNAMED_2_ADLT8612_I115_RT: R1.2(N2) U1.3
UNNAMED_2_ADLT8612_I115_SW1: C4.2(N2) L1.2(N2) U1.15 U1.16 U1.17 U1.18 U1.19
UNNAMED_2_ADLT8612_I115_TR: C3.1 U1.2
UNNAMED_2_CAP_I50_N1: C6.1 Q1.3 R5.2(N2) R6.1
UNNAMED_2_DIOLED_I132_N: DS1.C R46.2(N2)
UNNAMED_2_RES_I24_N1: R2.1 R3.2(N2) U1.4
UNNAMED_2_RES_I51_N2: Q1.2(E) R7.2(N2)
UNNAMED_2_RES_I53_N1: Q1.1 R8.2(N2) R9.1
UNNAMED_3_741G04_I85_Y: R70.1 U12.4(Y)
UNNAMED_3_ADCMP392_I76_IN: R66.1 R67.2(N2) R68.1 U11.3 U11.5
UNNAMED_3_ADCMP392_I76_OUT: R68.2(N2) R69.1 U11.1 U11.7 U12.2
UNNAMED_3_CN2P_I67_N2: D5.A(P) P12.2(N2) Q3.3 R71.1
UNNAMED_3_CN40PV2_I40_N8: JP4.1 P3.16
UNNAMED_3_CN40PV2_I40_N11: JP4.3 P3.22
UNNAMED_3_CN40PV2_I41_N7: JP2.1 P3.13
UNNAMED_3_CN40PV2_I41_N8: JP3.1 P3.15
UNNAMED_3_CN40PV2_I41_N16: DS2.A(P) P3.31
UNNAMED_3_CN40PV2_I41_N17: DS3.A(P) P3.33
UNNAMED_3_DIOLED_I48_N: DS2.C R20.2(N2)
UNNAMED_3_DIOLED_I49_N: DS3.C R21.2(N2)
UNNAMED_3_DIOLED_I84_N: DS4.C R71.2(N2)
UNNAMED_3_RES_I68_N2: Q3.1 R70.2(N2)
UNNAMED_3_RES_I87_N2: P3.11 R19.2(N2) S1.2(B)
UNNAMED_4_ADLT6015_I86_: A2.4 R26.1 R29.1 R75.1
UNNAMED_4_ADLT6015_I86__1: A2.3 JP5.2(COM)
UNNAMED_4_ADLT6015_I86_OUT: A2.1 D2.C R33.2(N2) R41.1
UNNAMED_4_ADLT6015_I87_V: A1.2(V-) A2.2(V-) C30.2(N2) C34.2(N2) JP1.2(COM)
UNNAMED_4_ADLT6015_I97_: A1.4 R27.1 R30.1 R74.1
UNNAMED_4_ADLT6015_I97_OUT: A1.1 D3.C R34.2(N2) R35.1
UNNAMED_4_ADLT8609_I129_BST: C31.2(N2) U5.1
UNNAMED_4_ADLT8609_I129_INTVCC: C27.1 U5.3
UNNAMED_4_ADLT8609_I129_PG: R24.1 U5.8
UNNAMED_4_ADLT8609_I129_RT: R22.1 U5.4
UNNAMED_4_ADLT8609_I129_TR: C28.1 U5.7
UNNAMED_4_ADLTC1983X_I10_C: C40.2(N2) U6.4
UNNAMED_4_ADLTC1983X_I10_C_1: C40.1 U6.3
UNNAMED_4_ADLTC1983X_I10_SHDNN: R28.2(N2) R31.2(N2) R32.1 U6.6
UNNAMED_4_CAP_I64_N1: C32.1 R23.1 R25.1 U5.6
UNNAMED_4_CAP_I177_N2: C38.2(N2) R33.1
UNNAMED_4_CAP_I182_N2: C39.2(N2) R34.1
UNNAMED_4_IND_I45_N1: C31.1 L2.1 U5.2
UNNAMED_4_LINLT3092_I168_OUT1: R47.1 U8.2 U8.3 U8.4
UNNAMED_4_LINLT3092_I168_SET: R45.2(N2) U8.5(SET)
UNNAMED_4_RES_I70_N2: Q2.2(E) R44.2(N2)
UNNAMED_6_AD568XRV2_I36_VREF: C56.1 C57.1 R65.2(N2) U10.9(VREF)
UNNAMED_6_AD71244_I19_AIN0: R59.2(N2) U9.4
UNNAMED_6_AD71244_I19_AIN1: R56.2(N2) U9.5
UNNAMED_6_AD71244_I19_AIN2: R60.2(N2) U9.8
UNNAMED_6_AD71244_I19_AIN3: R50.2(N2) U9.9
UNNAMED_6_AD71244_I19_AIN4: R55.2(N2) U9.16
UNNAMED_6_AD71244_I19_AIN5: R61.2(N2) U9.17
UNNAMED_6_AD71244_I19_AIN6: R63.2(N2) U9.20
UNNAMED_6_AD71244_I19_AIN7: R62.2(N2) U9.21
UNNAMED_6_AD71244_I19_CLK: R64.1 TP7.1(N1) U9.31
UNNAMED_6_AD71244_I19_REFOUT: C50.2(N2) U9.22
UNNAMED_6_AD71244_I19_REGCAPA: C52.1 U9.24
UNNAMED_6_AD71244_I19_REGCAPD: C51.1 U9.1
UNNAMED_6_CNTP1P_I52_N1: R54.2(N2) TP6.1(N1) U9.27(SYNC_N)
UNNAMED_6_RES_I2_N1: R52.2(N2) R53.1 R55.1
UNNAMED_6_RES_I4_N1: R48.2(N2) R49.1 R50.1
UNNAMED_6_RES_I53_N2: R57.2(N2) R58.1 R62.1
VDAC: JP5.1 TP8.1(N1) U10.10
VOUT: C21.2(N2) D1.3(N3) P7.2(N2) P8.2(N2) Q2.3 R9.2(N2) R17.2(N2) R18.2(N2) R52.1 VOUT.1(N1)
VPOT: A1.3 R43.4 TP4.1(N1)
VREF: C43.1 C44.1 JP5.3 R14.5 R43.5 R43.6 R65.1 R66.2(N2) TP9.1(N1) U9.12
VSET: C11.2(N2) C13.2(N2) D1.1 D1.2 D2.A(P) D3.A(P) R29.2(N2) R30.2(N2) R35.2(N2) R41.2(N2) R42.2(N2) R45.1 R47.2(N2) R74.2(N2) R75.2(N2) U2.7 U3.7
WP: P9.2 U4.7(WP) U7.7(WP)

Pads without a net: C39 1; D4 2; P3 7 12 18 29 32 35 36 37 38 40; P10 2 4 5 6 8; R14 7; R43 7; U5 5; U8 1 6; U9 25; U12 1

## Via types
v1: diameter 0.61, hole 0.305, TOP to BOTTOM, 957 vias

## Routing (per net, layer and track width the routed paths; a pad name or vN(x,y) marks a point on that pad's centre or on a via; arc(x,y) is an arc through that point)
3V3A: length 142.9
  TOP w0.305: U9.26 51.92,51.35 51.94,51.37 ; 51.94,51.37 51.94,51.22 51.93,51.22 51.93,50.78 ; 51.94,51.37 51.99,51.42 51.99,51.96 C48.2 ; U10.1 71.3,53.67 72.05,53.67 72.49,53.23 ; P10.10 1.4,62.23 1.4,56.39 6.64,51.14 R19.1 ; 66.02,64.25 65.91,64.35 65.91,65.28 65.67,65.52 U7.8 ; U4.8 49.54,65.13 49.54,65.14 C24.1
  TOP w0.508: 66.02,64.25 C22.1 66.02,62.59 ; E1.1 v1(71.79,57.07) ; E1.1 v1(71.79,59.29) ; E1.1 v1(70.68,58.18) ; C23.1 66.02,62.59 ; 66.02,62.59 v1(66.99,62.59) ; v1(55.36,52.56) C49.1 C48.2 ; R39.2 v1(60.47,68.31) ; R38.1 v1(78.62,63.61) ; R40.2 v1(60.47,66.66) ; R36.1 v1(78.62,67.04) ; C46.1 v1(49.7,63.48) ; C46.1 v1(48.71,62.49) ; C46.1 C24.1 48.71,66.52 R72.1 ; R37.1 v1(78.62,65.39) ; R73.1 52.67,68.37 53.3,67.73 v1(53.3,67.01) ; v1(54.45,55.75) R54.1 ; 72.49,53.23 C54.1 73.46,51.73 C55.1 v1(72.28,51.71)
  TOP w0.635: R38.1 R37.1 R36.1
  L3_VCC w0.635: 2.29,63.91 P10.10 1.5,63.12 ; P3.17 36.07,72.71 ; P3.17 36.07,70.55 ; P3.17 34.99,71.63 ; P3.17 37.15,71.63 ; 14.67,71.63 P3.1 ; P3.1 15.75,70.55 ; P3.1 15.75,72.71 ; P3.1 16.83,71.63
  L3_VCC w0.762: P9.1 112.84,23.56 112.84,30.55 109.35,34.04 109.35,40.39 112.9,43.94 112.9,53.72 104.28,62.34 104.28,66.92 100.71,70.49 81.18,70.49 79.02,68.33
3V3D: length 15.3
  TOP w0.305: 73.38,54.68 C53.1 ; 73.38,54.68 U10.3 ; 73.38,54.68 73.38,54.48 73.07,54.18 U10.2 ; 46.8,50.04 47.33,50.04 47.73,49.64 U9.2
  TOP w0.508: E1.2 v1(73.39,59.29) ; E1.2 v1(73.39,57.07) ; E1.2 v1(74.5,58.18) ; C53.1 v1(73.45,55.96) ; v1(47.24,51.71) C47.2 C45.1 46.28,50.04 46.8,50.04
  BOTTOM w0.762: v1(73.45,55.96) 73.41,55.91 73.39,55.93 v1(73.39,57.07)
5V_RPI: length 67.3
  TOP w0.305: C32.2 9.3,53 R25.2 10.29,50.67 10.67,50.29 21.59,50.29 22.1,50.8 22.1,55.88 ; U12.5 v1(81.8,64.5)
  TOP w0.508: DS4.A 102.05,68.02 101.49,67.45 98.04,67.45 ; R31.1 62.32,39.28 62.74,38.86 66.8,38.86 v1(66.92,38.99) 66.97,39.03 C37.2 66.97,40.13 66.92,40.18 U6.1 ; R69.2 v1(88.77,63.88) ; U11.8 v1(83.31,68.33) ; R24.2 v1(13.46,51.31)
  TOP w0.635: L2.2 19.65,66.87 ; L2.2 20.64,64.77 ; L2.2 19.65,62.67 ; C35.1 19.81,62.18 ; C35.1 19.81,58.98 ; C35.1 20.85,60.58 ; D5.C 97.8,70.46 ; D5.C 97.8,68.73 ; D5.C 97.09,69.6 ; 96.96,73.91 P12.1 98.04,72.83 ; 19.81,56.15 C36.1 ; C36.1 20.87,57.4 ; C36.1 19.81,58.66
  BOTTOM w0.635: 14.67,74.17 P3.2 ; P3.2 15.75,73.09 ; P3.2 16.83,74.17 ; 18.29,73.09 P3.4 ; P3.4 19.37,74.17 ; P3.4 17.21,74.17
  vias: v1(21.21,58.17) v1(21.21,57.4) v1(21.21,56.64) v1(22.1,58.17) v1(22.1,57.4) v1(22.1,56.64) v1(96.27,68.2) v1(97.03,68.2) v1(97.8,68.21)
AGND: length 232
  TOP w0.203: 2.35,33.71 2.29,33.66
  TOP w0.305: U4.4 57.81,67.08 v1(58.04,67.31) ; U9.3 47.26,49.14 v1(47.12,49.28) ; U4.3 v1(58.04,66.43) ; v1(73.7,68.59) P4.1 72.57,67.78 72.26,67.47 U7.4 ; U9.19 53.84,47.64 v1(54.1,47.37) 53.87,47.14 U9.18 ; U9.14 v1(51.42,45.02) ; v1(51.42,45.02) 51.92,45.52 U9.15 ; v1(51.42,45.02) 50.92,45.52 U9.13 ; U9.10 49.42,45.24 v1(49.65,45.01) 49.92,45.28 U9.11 ; U10.5 72.19,55.68 72.39,55.88 v1(72.45,55.88) ; U9.23 54.08,49.64 v1(54.1,49.66) ; U12.3 v1(85.58,65.8) ; U4.1 v1(56.67,64.36) ; U9.6 47.56,47.64 v1(47.3,47.37) 47.53,47.14 U9.7 ; v1(69.98,55.5) 70.3,55.18 U10.4 ; U4.2 57.88,65.78 v1(58.04,65.62)
  TOP w0.457: R26.2 v1(85.22,43.81) ; v1(59.05,52.2) R58.2 ; C30.1 v1(84.5,42.97)
  TOP w0.508: 2.41,33.53 2.35,33.6 R46.1 ; R27.2 v1(85.1,57.77) ; R20.1 v1(6.6,68.58) ; R10.2 v1(92.98,20.72) ; P6.1 v1(72.46,62.47) ; C5.2 v1(23.35,40.24) ; C28.2 v1(11.81,51.31) ; C38.1 v1(89.23,35.81) ; C43.2 C44.2 v1(49.55,41.3) ; v1(88.77,73.91) R67.1 88.18,72.14 U11.4 ; C24.2 v1(46.12,65.14) ; R32.2 v1(62.37,44.82) ; R49.2 v1(43.49,42.42) ; C34.1 v1(89.53,50.93) ; Q2.1 v1(76.12,46.43) ; C11.1 v1(50.28,7.92) ; C41.2 v1(68.71,45.85) ; P5.1 v1(72.46,64.66) ; C13.1 v1(92.07,8.9) ; C52.2 v1(57.78,50.95) ; C27.2 v1(12.7,65.36) ; R22.2 v1(11.18,65.41) ; Q3.2 v1(79.5,60.51) ; R53.2 55.74,41.8 v1(55.88,41.66) ; 51.18,22.35 51.01,22.19 R51.2 ; U6.5 v1(65.53,42.68) ; C46.2 v1(46.12,63.48) ; C37.1 v1(64.19,40.08) ; C50.1 v1(57.78,49.4) ; JP1.3 v1(87.85,47.78) ; R21.1 v1(6.73,66.29) ; D4.3 v1(71.37,46.86) ; C33.1 v1(82.64,56.25)
  TOP w0.635: C42.2 v1(36.44,50.89) ; v1(43.59,53.32) C51.2 C47.1 ; C47.1 v1(43.59,51.71) ; C47.1 C45.2 v1(43.59,50.15) ; C55.2 v1(76.05,51.71) ; R64.2 v1(44.49,56.39) ; C53.2 v1(76.07,54.76) ; P1.2 3.68,16.43 ; P1.2 2.54,15.29 ; P1.2 4.83,15.29 ; P1.2 3.68,14.14 ; P2.3 8.12,30.37 ; P2.3 6.37,29.47 ; P2.3 8.12,28.56 ; P2.3 9.88,29.47 ; C54.2 v1(76.08,53.23) ; C48.1 C49.2 v1(55.52,55.48) ; 5.02,23.01 P2.2 ; P2.2 4.12,24.77 ; P2.2 5.92,24.77 ; P2.2 5.02,26.52 ; v1(62.08,52.56) C57.2 C56.2 v1(62.08,54.08) ; v1(63.44,64.12) C22.2 64.42,62.59 C23.2 v1(63.44,62.59) ; C29.1 v1(82.64,41.4) ; 2.79,46.19 v1(2.79,43.94)
  L2_GND w0.635: 20.83,74.17 21.91,74.17 ; 20.83,74.17 20.83,73.09 ; 20.83,74.17 19.75,74.17 ; 3.56,63.91 3.56,63.12 4.34,63.12 ; P3.30 52.39,74.17 ; P3.30 50.23,74.17 ; P3.30 51.31,73.09 ; 30.99,73.09 P3.14 ; P3.14 29.91,74.17 ; P3.14 32.07,74.17 ; 98.48,24.89 R43.1 ; R43.1 99.49,25.91 ; R43.1 99.49,23.88 ; 101.49,49.4 R14.2 101.49,51.44 ; P3.39 64.01,72.71 ; P3.39 65.09,71.63 ; P3.39 62.93,71.63 ; P3.39 64.01,70.55 ; AGND.1 41.78,8.26 ; AGND.1 44.83,5.21 ; AGND.1 38.73,5.21 ; AGND.1 41.78,2.16 ; 110.87,15.43 P9.3 ; P9.3 110.87,17.59 ; P9.3 111.95,16.51 ; P9.3 109.79,16.51 ; 3.56,61.85 4.57,61.85 ; 56.39,73.09 P3.34 ; P3.34 57.47,74.17 ; P3.34 55.31,74.17 ; 45.15,71.63 P3.25 ; P3.25 46.23,70.55 ; P3.25 47.31,71.63 ; P3.25 46.23,72.71 ; P3.9 26.99,71.63 ; P3.9 25.91,72.71 ; P3.9 24.83,71.63 ; P3.9 25.91,70.55 ; 3.68,14.14 P1.2 ; P1.2 4.83,15.29 ; P1.2 3.68,16.43 ; P1.2 2.54,15.29 ; P2.2 5.02,26.52 ; P2.2 5.92,24.77 ; P2.2 4.12,24.77 ; P2.2 5.02,23.01 ; P3.20 39.69,74.17 ; P3.20 38.61,73.09 ; P3.20 37.53,74.17 ; 8.12,28.56 P2.3 ; P2.3 9.88,29.47 ; P2.3 6.37,29.47 ; P2.3 8.12,30.37 ; 101.49,23.88 R43.2 101.49,25.91
  L3_VCC w0.635: 62.93,71.63 P3.39 ; P3.39 64.01,72.71 ; P3.39 65.09,71.63 ; P3.39 64.01,70.55 ; P3.30 52.39,74.17 ; P3.30 51.31,73.09 ; P3.30 50.23,74.17 ; P3.34 57.47,74.17 ; P3.34 55.31,74.17 ; P3.34 56.39,73.09 ; 38.73,5.21 AGND.1 ; AGND.1 41.78,2.16 ; AGND.1 44.83,5.21 ; P3.25 47.31,71.63 ; P3.25 46.23,70.55 ; P3.25 46.23,72.71 ; P3.25 45.15,71.63
  BOTTOM w0.635: P3.25 46.23,72.71 ; P3.25 45.15,71.63 ; P3.25 47.31,71.63 ; P3.25 46.23,70.55 ; P3.39 64.01,72.71 ; P3.39 62.93,71.63 ; P3.39 65.09,71.63 ; P3.39 64.01,70.55 ; 101.49,51.44 R14.2 101.49,49.4 ; P3.30 52.39,74.17 ; P3.30 50.23,74.17 ; P3.30 51.31,73.09 ; 37.53,74.17 P3.20 ; P3.20 38.61,73.09 ; P3.20 39.69,74.17 ; P3.14 32.07,74.17 ; P3.14 29.91,74.17 ; P3.14 30.99,73.09 ; 55.31,74.17 P3.34 ; P3.34 57.47,74.17 ; P3.34 56.39,73.09 ; 25.91,70.55 P3.9 ; P3.9 26.99,71.63 ; P3.9 25.91,72.71
  vias: v1(11.43,32.89) v1(12.7,59.31) v1(12.7,58.29) v1(13.33,58.8) v1(13.97,59.31) v1(13.99,58.31) v1(15.49,61.09) v1(15.49,60.2) v1(15.49,59.31) v1(15.49,58.42) v1(15.49,57.53) v1(15.49,56.64) v1(19.05,54.99) v1(19.05,54.23) v1(20.32,54.48) v1(20.32,53.59) v1(20.32,52.7) v1(20.32,51.82) v1(21.34,54.48) v1(21.34,53.59) v1(21.34,52.7) v1(21.34,51.82) v1(21.34,35.81) v1(21.34,34.92) v1(22.23,35.81) v1(22.23,34.92) v1(23.24,35.81) v1(23.24,34.92) v1(24.26,35.81) v1(24.26,34.92) v1(25.15,35.81) v1(25.15,34.92) v1(25.78,33.27) v1(26.29,29.34) v1(26.29,28.19) v1(26.29,27.05) v1(26.67,33.27) v1(26.67,22.48) v1(26.67,21.21) v1(27.34,35.81) v1(27.34,34.8) v1(27.34,33.78) v1(27.34,29.34) v1(27.34,28.19) v1(27.34,27.05) v1(27.94,22.48) v1(27.94,21.21) v1(29.21,23.75) v1(29.21,22.48) v1(29.21,21.21) v1(29.21,19.94) v1(30.48,23.75) v1(30.48,22.48) v1(30.48,21.21) v1(30.48,19.94) v1(31.75,23.75) v1(31.75,22.48) v1(31.75,21.21) v1(31.75,19.94) v1(33.02,23.75) v1(33.02,22.48) v1(33.02,21.21) v1(33.02,19.94) v1(34.29,23.75) v1(34.29,22.48) v1(34.29,21.21) v1(34.29,19.94) v1(35.56,21.21) v1(35.56,19.94) v1(36.83,21.21) v1(36.83,19.94) v1(37.97,7.62) v1(37.97,6.35) v1(37.97,5.08) v1(37.97,3.81) v1(37.97,2.67) v1(38.1,23.75) v1(38.1,22.48) v1(38.1,21.21) v1(38.1,19.94) v1(38.61,6.98) v1(38.61,5.71) v1(38.61,4.45) v1(38.61,3.17) v1(38.61,2.03) v1(39.12,7.75) v1(39.37,23.75) v1(39.37,22.48) v1(39.37,21.21) v1(39.37,19.94) v1(39.37,2.67) v1(39.37,1.4) v1(40,2.03) v1(40.64,23.75) v1(40.64,22.48) v1(40.64,21.21) v1(40.64,19.94) v1(40.64,1.4) v1(41.27,2.03) v1(41.91,23.75) v1(41.91,22.48) v1(41.91,21.21) v1(41.91,19.94) v1(42.04,1.4) v1(42.67,2.03) v1(43.18,23.75) v1(43.43,1.4) v1(44.07,2.03) v1(44.2,7.62) v1(44.45,23.75) v1(44.7,2.79) v1(44.7,1.4) v1(44.83,6.86) v1(44.83,4.06) v1(45.09,5.84) v1(45.34,3.43) v1(45.34,2.03) v1(45.47,4.7) v1(45.72,6.48) v1(45.97,5.46) v1(45.97,4.06) v1(45.97,2.79) v1(45.97,1.4) v1(46.61,4.7) v1(46.61,3.43) v1(46.61,2.03) v1(49.4,49.53) v1(49.4,48.39) v1(49.4,47.12) v1(50.67,49.53) v1(50.67,48.39) v1(50.67,47.12) v1(51.94,49.53) v1(51.94,48.39) v1(51.94,47.12) v1(53.34,20.32) v1(58.29,25.02) v1(58.29,23.75) v1(58.29,22.48) v1(59.56,25.02) v1(59.56,23.75) v1(59.56,22.48) v1(60.83,25.02) v1(60.83,23.75) v1(60.83,22.48) v1(62.1,25.02) v1(62.1,23.75) v1(62.1,22.48) v1(63.37,25.02) v1(63.37,23.75) v1(63.37,22.48) v1(64.64,25.02) v1(64.64,23.75) v1(64.64,22.48) v1(65.91,25.02) v1(65.91,23.75) v1(65.91,22.48) v1(67.18,25.02) v1(67.18,23.75) v1(67.18,22.48) v1(67.18,21.21) v1(68.45,25.02) v1(68.45,23.75) v1(68.45,22.48) v1(68.45,21.21) v1(68.45,19.94) v1(68.45,18.67) v1(69.72,25.02) v1(69.72,23.75) v1(69.72,22.48) v1(69.72,21.21) v1(69.72,19.94) v1(69.72,18.67) v1(70.48,2.79) v1(70.99,25.02) v1(70.99,23.75) v1(70.99,22.48) v1(70.99,21.21) v1(70.99,19.94) v1(70.99,18.67) v1(71.75,5.21) v1(71.75,3.94) v1(71.75,2.79) v1(72.26,25.02) v1(72.26,23.75) v1(72.26,22.48) v1(72.26,21.21) v1(72.26,19.94) v1(72.26,18.67) v1(73.53,25.02) v1(73.53,23.75) v1(73.53,22.48) v1(73.53,21.21) v1(73.53,19.94) v1(74.8,25.02) v1(74.8,23.75) v1(74.8,22.48) v1(74.8,21.21) v1(74.8,19.94) v1(76.07,25.02) v1(76.07,23.75) v1(76.07,22.48) v1(76.07,21.21) v1(76.07,19.94) v1(77.34,25.02) v1(77.34,23.75) v1(77.34,22.48) v1(77.34,21.21) v1(77.34,19.94) v1(78.61,25.02) v1(78.61,23.75) v1(78.61,22.48) v1(78.61,21.21) v1(78.61,19.94) v1(79.88,25.02) v1(79.88,23.75) v1(79.88,22.48) v1(79.88,21.21) v1(79.88,19.94) v1(81.15,25.02) v1(81.15,23.75) v1(81.15,22.48) v1(81.15,21.21) v1(81.15,19.94) v1(82.42,25.02) v1(82.42,23.75) v1(82.42,22.48) v1(82.42,21.21) v1(82.42,19.94) v1(83.69,25.02) v1(83.69,23.75)
VIN: length 17.9
  TOP w0.508: R48.1 v1(47.58,41.45) ; v1(84.24,54.24) C33.2 85.85,55.24 A1.5 ; C29.2 84.41,40.09 A2.5
  TOP w0.635: C29.2 v1(84.24,41.4)
  BOTTOM w0.635: 2.54,10.29 P1.1 ; P1.1 3.68,11.43 ; P1.1 3.68,9.14 ; P1.1 4.83,10.29 ; 10.92,22.5 P2.1 ; P2.1 10.92,27.03 ; P2.1 11.82,24.77 ; P2.1 10.02,24.77
  vias: v1(14.73,54.1) v1(14.69,53.21) v1(14.69,52.32) v1(14.71,51.44) v1(20.19,26.29) v1(20.19,25.15) v1(20.19,22.35) v1(20.19,21.21) v1(21.34,26.29) v1(21.34,25.15) v1(21.34,22.35) v1(21.34,21.21) v1(22.48,26.29) v1(22.48,25.15) v1(22.48,22.35) v1(22.48,21.21)
A0: length 6.6
  TOP w0.305: U7.1 70.9,64.23 71.84,63.29 P6.2 75.31,63.29 R38.2
A1: length 5.1
  TOP w0.305: R37.2 75.56,65.47 P5.2 73.28,65.47 72.58,66.17 U7.2
A2: length 4.8
  TOP w0.305: R36.2 75.56,66.97 P4.2 72.57,66.97 72.42,66.82 U7.3
CS0: length 23.2
  TOP w0.203: v1(44.45,65.91) 44.83,66.29 44.83,73.03 43.69,74.17 ; JP2.3 v1(32.08,64.57)
  BOTTOM w0.203: v1(44.45,65.91) 33.43,65.91 v1(32.08,64.57)
CS1: length 21.6
  TOP w0.203: JP3.3 v1(35.51,64.57) ; P3.26 47.5,72.9 47.5,67.94 v1(45.47,65.91)
  BOTTOM w0.203: v1(45.47,65.91) 45.47,65.79 44.96,65.28 36.22,65.28 v1(35.51,64.57)
CS_ADC: length 26
  TOP w0.203: U9.32 48.93,50.84 48.93,52.8 47.5,54.23 41.4,54.23 31.24,64.39 JP2.2
CS_DAC: length 42.1
  TOP w0.203: JP3.2 34.67,64.39 38.73,60.33 45.66,60.33 48.01,57.98 v1(48.01,55.75)
  TOP w0.305: v1(65.41,55.5) 65.73,55.18 U10.7 66.98,55.18
  BOTTOM w0.203: v1(48.01,55.75) 48.13,55.63 48.13,53.54 48.46,53.21 50.16,53.21 50.55,53.59 56.64,53.59 58.55,55.5 v1(65.41,55.5)
ID_SC: length 10.5
  TOP w0.305: U4.6 51.96,66.43 52.36,66.84 52.36,67.44 R73.2 50.04,69.76 50.04,72.9 P3.28
ID_SD: length 6.1
  TOP w0.305: U4.5 49.84,67.08 R72.2 48.77,68.41 P3.27
ILIM+: length 123.8
  TOP w0.356: 45.34,16.51 45.35,16.52 U2.16
  TOP w0.635: R14.6 109.52,50.39 TP1.1
  L3_VCC w0.508: v1(51.82,2.54) 52.2,2.54 52.83,1.91 97.66,1.91 98.55,2.79 98.55,21.73 97.32,22.96 92.92,22.96 92,23.89 92,29.9 93.78,31.67 93.78,46.79 98.93,51.94 103.97,51.94 R14.4 105.49,50.45 106.68,51.64 108.27,51.64 R14.6
  BOTTOM w0.635: R18.1 55.64,17.5 ; R18.1 54.86,16.76 ; R18.1 55.64,16.03
  vias: v1(18.16,15.24) v1(18.16,13.97) v1(18.16,12.7) v1(18.16,11.43) v1(18.16,10.16) v1(18.16,8.89) v1(18.16,7.62) v1(18.16,6.35) v1(18.16,5.08) v1(18.16,3.81) v1(18.16,2.54) v1(19.43,15.24) v1(19.43,13.97) v1(19.43,12.7) v1(19.43,11.43) v1(19.43,10.16) v1(19.43,8.89) v1(19.43,7.62) v1(19.43,6.35) v1(19.43,5.08) v1(19.43,3.81) v1(19.43,2.54) v1(20.83,15.24) v1(20.83,13.97) v1(20.83,12.7) v1(20.83,11.43) v1(20.83,10.16) v1(20.83,8.89) v1(20.83,7.62) v1(20.83,6.35) v1(20.83,5.08) v1(20.83,3.81) v1(20.83,2.54) v1(22.23,15.24) v1(22.23,13.97) v1(22.23,12.7) v1(22.23,11.43) v1(22.23,10.16) v1(22.23,8.89) v1(22.23,7.62) v1(22.23,6.35) v1(22.23,5.08) v1(22.23,3.81) v1(22.23,2.54) v1(23.49,15.24) v1(23.49,13.97) v1(23.49,12.7) v1(23.49,11.43) v1(23.49,10.16) v1(23.49,8.89) v1(23.49,7.62) v1(23.49,6.35) v1(23.49,5.08) v1(23.49,3.81) v1(23.49,2.54) v1(24.89,15.24) v1(24.89,13.97) v1(24.89,12.7) v1(24.89,11.43) v1(24.89,10.16) v1(24.89,8.89) v1(24.89,7.62) v1(24.89,6.35) v1(24.89,5.08) v1(24.89,3.81) v1(24.89,2.54) v1(26.16,15.24) v1(26.16,13.97) v1(26.16,12.7) v1(26.16,11.43) v1(26.16,10.16) v1(26.16,8.89) v1(26.16,7.62) v1(26.16,6.35) v1(26.16,5.08) v1(26.16,3.81) v1(26.16,2.54) v1(27.56,15.24) v1(27.56,13.97) v1(27.56,12.7) v1(27.56,11.43) v1(27.56,10.16) v1(27.56,8.89) v1(27.56,7.62) v1(27.56,6.35) v1(27.56,5.08) v1(27.56,3.81) v1(27.56,2.54) v1(28.83,15.24) v1(28.83,13.97) v1(28.83,12.7) v1(28.83,11.43) v1(28.83,10.16) v1(28.83,8.89) v1(28.83,7.62) v1(28.83,6.35) v1(28.83,5.08) v1(28.83,3.81) v1(28.83,2.54) v1(30.23,15.24) v1(30.23,13.97) v1(30.23,12.7) v1(30.23,11.43) v1(30.23,10.16) v1(30.23,8.89) v1(30.23,7.62) v1(30.23,6.35) v1(30.23,5.08) v1(30.23,3.81) v1(30.23,2.54) v1(31.5,15.24) v1(31.5,13.97) v1(31.5,12.7) v1(31.5,11.43) v1(31.5,10.16) v1(31.5,8.89) v1(31.5,7.62) v1(31.5,6.35) v1(31.5,5.08) v1(31.5,3.81) v1(31.5,2.54) v1(32.77,13.97) v1(32.77,12.7) v1(32.77,11.43) v1(32.77,10.16) v1(32.77,8.89) v1(32.77,7.62) v1(32.77,6.35) v1(32.77,5.08) v1(32.77,3.81) v1(32.77,2.54) v1(34.04,13.97) v1(34.04,12.7) v1(34.04,11.43) v1(34.04,10.16) v1(34.04,8.89) v1(34.04,7.62) v1(34.04,6.35) v1(34.04,5.08) v1(34.04,3.81) v1(34.04,2.54) v1(35.31,13.97) v1(35.31,10.16) v1(35.31,8.89) v1(35.31,7.62) v1(35.31,6.35) v1(35.31,5.08) v1(35.31,3.81) v1(35.31,2.54) v1(36.58,13.97) v1(36.58,10.16) v1(36.58,8.89) v1(36.58,7.62) v1(36.58,6.35) v1(36.58,5.08) v1(36.58,3.81) v1(36.58,2.54) v1(37.85,13.97) v1(37.85,12.7) v1(37.85,11.43) v1(37.85,10.16) v1(39.12,13.97) v1(39.12,12.7) v1(39.12,11.43) v1(39.12,10.16) v1(40.39,13.97) v1(40.39,12.7) v1(40.39,11.43) v1(40.39,10.16) v1(41.66,13.97) v1(41.66,12.7) v1(41.66,11.43) v1(41.66,10.16) v1(42.93,13.97) v1(42.93,12.7) v1(42.93,11.43) v1(42.93,10.16) v1(44.2,13.97) v1(44.2,12.7) v1(44.2,11.43) v1(44.2,10.16) v1(45.34,16.13) v1(45.34,14.99) v1(45.47,13.97) v1(45.47,11.43) v1(45.47,10.16) v1(45.47,8.89) v1(46.15,16.76) v1(46.15,15.62) v1(46.15,14.48) v1(46.74,11.43) v1(46.89,16.76) v1(46.89,15.62) v1(46.89,14.48) v1(47.62,16.76) v1(47.62,15.62) v1(47.62,14.48) v1(48.06,7.62) v1(48.06,6.35) v1(48.18,5.09) v1(48.18,3.82) v1(48.15,2.57) v1(48.36,16.76) v1(48.36,15.62) v1(48.36,14.48) v1(49.1,16.76) v1(49.1,15.62) v1(49.1,14.48) v1(49.28,7.62) v1(49.28,6.35) v1(49.28,5.08) v1(49.28,3.81) v1(49.28,2.54) v1(49.78,16.89) v1(49.78,15.62) v1(49.78,14.35) v1(50.55,18.16) v1(50.55,16.89) v1(50.55,15.62) v1(50.55,14.35) v1(50.55,13.08) v1(50.55,6.35) v1(50.55,5.08) v1(50.55,3.81) v1(50.55,2.54) v1(51.82,18.16) v1(51.82,16.89) v1(51.82,15.62) v1(51.82,14.35) v1(51.82,13.08) v1(51.82,11.43) v1(51.82,8.89) v1(51.82,5.08) v1(51.82,3.81) v1(53.09,18.16) v1(53.09,16.89) v1(53.09,15.62) v1(53.09,14.35) v1(53.09,13.08) v1(53.09,11.43) v1(54.23,18.16) v1(54.23,16.89) v1(54.23,15.62) v1(54.23,14.35) v1(54.23,13.08)
ILIM-: length 121.1
  TOP w0.356: v1(46.99,8.03) R12.1 R13.2
  TOP w0.762: TP2.1 R14.1
  L3_VCC w0.508: v1(46.99,8.03) 46.99,6.34 47.37,5.96 47.37,1.65 47.88,1.14 98.68,1.14 99.57,2.03 99.57,21.72 97.61,23.67 93.22,23.67 92.71,24.18 92.71,29.34 94.49,31.11 94.49,45.42 R14.1
IMON: length 87.5
  TOP w0.305: v1(90.04,19.57) 89.89,19.42 U3.10 ; v1(50.93,21.34) 50.93,20.6 R11.1 49.88,19.56 49.55,19.56 49.25,19.25 U2.10 ; v1(43.46,43.94) 43.46,45.33 43.74,45.61 R60.1
  L3_VCC w0.305: v1(90.04,19.57) 89.41,19.57 88.77,20.21 88.77,26.67 84.96,30.48 56.64,30.48 54.86,28.7 54.86,24.51 51.69,21.34 v1(50.93,21.34) 50.93,32.89 42.83,40.99 42.83,42.69 43.43,43.3 43.43,43.92 v1(43.46,43.94)
